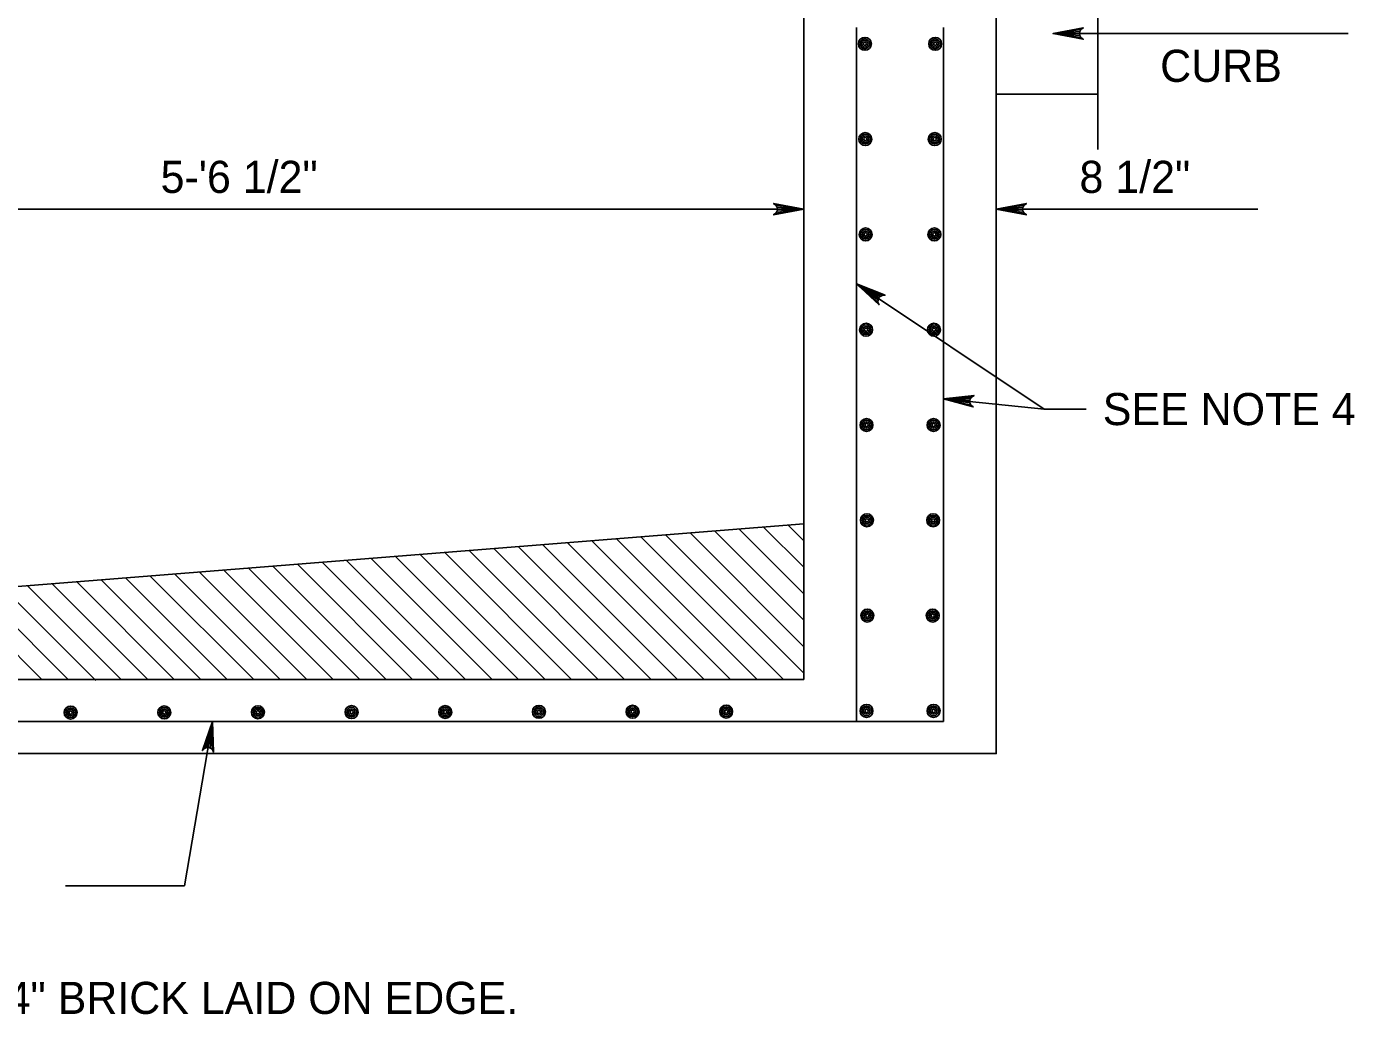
# Model space of a CAD drawing. Extents: x 2.4 to 9.7, y 1.1 to 11.2.
# Drawn here: x 7.045 to 9.526, y 8.136 to 9.981 of the extents above; entities that cross this region are included whole.
import ezdxf

# ---------------------------------------------------------------- set-up
doc = ezdxf.new("R2010")
doc.units = 0
for name, color, linetype in [('DETL-DIMS', 7, 'Continuous'), ('DETL-LINE', 7, 'Continuous'), ('DETL-NOTE', 7, 'Continuous'), ('DETL-PATT', 7, 'Continuous')]:
    doc.layers.add(name, color=color, linetype=linetype)

msp = doc.modelspace()

# ---------------------------------------------------------------- linework, layer by layer
at = {"layer": 'DETL-DIMS'}
for p, q in [((8.9629, 9.9678), (9.5146, 9.9678)), ((6.4511, 9.6398), (8.4972, 9.6398)), ((8.8568, 9.6398), (9.3453, 9.6398)), ((8.5958, 9.5003), (8.9462, 9.2664)), ((8.7582, 9.2855), (8.9462, 9.2664)), ((8.9462, 9.2664), (9.0251, 9.2664)), ((7.3923, 8.6829), (7.3404, 8.376)), ((7.3404, 8.376), (7.1175, 8.376))]:
    msp.add_line(p, q, dxfattribs=at)
for points in [[(8.9629, 9.9678), (9.0194, 9.9784), (9.0151, 9.9754), (9.0128, 9.9716), (9.0122, 9.9678), (9.0128, 9.964), (9.0151, 9.9602), (9.0194, 9.9572), (8.9629, 9.9678), (9.0151, 9.9602), (9.0128, 9.964), (8.9629, 9.9678), (9.0122, 9.9678), (9.0128, 9.9716), (8.9629, 9.9678), (9.0151, 9.9754)], [(8.4972, 9.6398), (8.4407, 9.6292), (8.4451, 9.6322), (8.4473, 9.636), (8.448, 9.6398), (8.4473, 9.6436), (8.4451, 9.6474), (8.4407, 9.6504), (8.4972, 9.6398), (8.4451, 9.6474), (8.4473, 9.6436), (8.4972, 9.6398), (8.448, 9.6398), (8.4473, 9.636), (8.4972, 9.6398), (8.4451, 9.6322)], [(8.8568, 9.6398), (8.9133, 9.6504), (8.9089, 9.6474), (8.9067, 9.6436), (8.906, 9.6398), (8.9067, 9.636), (8.9089, 9.6322), (8.9133, 9.6292), (8.8568, 9.6398), (8.9089, 9.6322), (8.9067, 9.636), (8.8568, 9.6398), (8.906, 9.6398), (8.9067, 9.6436), (8.8568, 9.6398), (8.9089, 9.6474)], [(8.5958, 9.5003), (8.6491, 9.4789), (8.6439, 9.4787), (8.6399, 9.4767), (8.6373, 9.4739), (8.6359, 9.4703), (8.6357, 9.4659), (8.6378, 9.4611), (8.5958, 9.5003), (8.6357, 9.4659), (8.6359, 9.4703), (8.5958, 9.5003), (8.6373, 9.4739), (8.6399, 9.4767), (8.5958, 9.5003), (8.6439, 9.4787)], [(8.7582, 9.2855), (8.8153, 9.2916), (8.8108, 9.2889), (8.8082, 9.2853), (8.8073, 9.2816), (8.8076, 9.2778), (8.8096, 9.2738), (8.8137, 9.2705), (8.7582, 9.2855), (8.8096, 9.2738), (8.8076, 9.2778), (8.7582, 9.2855), (8.8073, 9.2816), (8.8082, 9.2853), (8.7582, 9.2855), (8.8108, 9.2889)], [(7.3923, 8.6829), (7.3945, 8.6255), (7.3922, 8.6302), (7.3888, 8.633), (7.3851, 8.6342), (7.3813, 8.6341), (7.3772, 8.6324), (7.3736, 8.6286), (7.3923, 8.6829), (7.3772, 8.6324), (7.3813, 8.6341), (7.3923, 8.6829), (7.3851, 8.6342), (7.3888, 8.633), (7.3923, 8.6829), (7.3922, 8.6302)]]:
    msp.add_lwpolyline(points, dxfattribs=at)
at = {"layer": 'DETL-LINE'}
for p, q in [((8.8568, 8.6227), (8.8568, 10.6227)), ((8.4972, 8.7614), (8.4972, 10.5136)), ((9.0468, 10.2538), (9.0468, 9.7514)), ((8.5958, 8.6829), (8.5958, 9.979)), ((8.7582, 8.6829), (8.7582, 9.979)), ((9.0468, 9.8543), (8.8568, 9.8543)), ((6.4511, 8.8886), (8.4972, 9.052)), ((6.4511, 8.7614), (8.4972, 8.7614)), ((6.3547, 8.6829), (8.5958, 8.6829)), ((8.5958, 8.6829), (8.7582, 8.6829)), ((6.0916, 8.6227), (8.8568, 8.6227))]:
    msp.add_line(p, q, dxfattribs=at)
for centre, radius in [((8.6113, 9.9486), 0.0121), ((8.6113, 9.9486), 0.00909), ((8.6113, 9.9486), 0.00606), ((8.6113, 9.9486), 0.00303), ((8.7427, 9.9486), 0.0121), ((8.7427, 9.9486), 0.00909), ((8.7427, 9.9486), 0.00606), ((8.7427, 9.9486), 0.00303), ((8.6121, 9.7706), 0.0121), ((8.6121, 9.7706), 0.00909), ((8.6121, 9.7706), 0.00606), ((8.7419, 9.7706), 0.0121), ((8.7419, 9.7706), 0.00909), ((8.7419, 9.7706), 0.00606), ((8.6121, 9.7706), 0.00303), ((8.7419, 9.7706), 0.00303), ((8.6128, 9.5926), 0.0121), ((8.7412, 9.5926), 0.0121), ((8.6128, 9.5926), 0.00909), ((8.6128, 9.5926), 0.00606), ((8.6128, 9.5926), 0.00303), ((8.7412, 9.5926), 0.00909), ((8.7412, 9.5926), 0.00606), ((8.7412, 9.5926), 0.00303), ((8.6136, 9.4146), 0.0121), ((8.6136, 9.4146), 0.00909), ((8.6136, 9.4146), 0.00606), ((8.6136, 9.4146), 0.00303), ((8.7404, 9.4146), 0.0121), ((8.7404, 9.4146), 0.00909), ((8.7404, 9.4146), 0.00606), ((8.7404, 9.4146), 0.00303), ((8.6144, 9.2366), 0.0121), ((8.6144, 9.2366), 0.00909), ((8.6144, 9.2366), 0.00606), ((8.6144, 9.2366), 0.00303), ((8.7396, 9.2366), 0.0121), ((8.7396, 9.2366), 0.00909), ((8.7396, 9.2366), 0.00606), ((8.7396, 9.2366), 0.00303), ((8.6151, 9.0586), 0.0121), ((8.6151, 9.0586), 0.00909), ((8.6151, 9.0586), 0.00606), ((8.6151, 9.0586), 0.00303), ((8.7389, 9.0586), 0.0121), ((8.7389, 9.0586), 0.00909), ((8.7389, 9.0586), 0.00606), ((8.7389, 9.0586), 0.00303), ((8.6159, 8.8806), 0.0121), ((8.6159, 8.8806), 0.00909), ((8.6159, 8.8806), 0.00606), ((8.6159, 8.8806), 0.00303), ((8.7381, 8.8806), 0.0121), ((8.7381, 8.8806), 0.00909), ((8.7381, 8.8806), 0.00606), ((8.7381, 8.8806), 0.00303), ((7.1273, 8.6995), 0.0121), ((7.1273, 8.6995), 0.00909), ((7.3023, 8.6998), 0.0121), ((7.3023, 8.6998), 0.00909), ((7.4772, 8.7), 0.0121), ((7.4772, 8.7), 0.00909), ((7.6522, 8.7003), 0.0121), ((7.6522, 8.7003), 0.00909), ((7.8272, 8.7005), 0.0121), ((7.8272, 8.7005), 0.00909), ((8.0022, 8.7008), 0.0121), ((8.0022, 8.7008), 0.00909), ((8.1772, 8.701), 0.0121), ((8.1772, 8.701), 0.00909), ((8.3522, 8.7013), 0.0121), ((8.3522, 8.7013), 0.00909), ((8.6144, 8.7026), 0.0121), ((8.6144, 8.7026), 0.00909), ((8.6144, 8.7026), 0.00606), ((8.7396, 8.7026), 0.0121), ((8.7396, 8.7026), 0.00909), ((8.7396, 8.7026), 0.00606), ((7.1273, 8.6995), 0.00606), ((7.1273, 8.6995), 0.00303), ((7.3023, 8.6998), 0.00606), ((7.3023, 8.6998), 0.00303), ((7.4772, 8.7), 0.00606), ((7.4772, 8.7), 0.00303), ((7.6522, 8.7003), 0.00606), ((7.6522, 8.7003), 0.00303), ((7.8272, 8.7005), 0.00606), ((7.8272, 8.7005), 0.00303), ((8.0022, 8.7008), 0.00606), ((8.0022, 8.7008), 0.00303), ((8.1772, 8.701), 0.00606), ((8.1772, 8.701), 0.00303), ((8.3522, 8.7013), 0.00606), ((8.3522, 8.7013), 0.00303), ((8.6144, 8.7026), 0.00303), ((8.7396, 8.7026), 0.00303)]:
    msp.add_circle(centre, radius, dxfattribs=at)
at = {"layer": 'DETL-PATT'}
for p, q in [((8.2388, 9.0313), (8.4972, 8.773)), ((8.2847, 9.035), (8.4972, 8.8225)), ((8.3305, 9.0387), (8.4972, 8.872)), ((8.3764, 9.0423), (8.4972, 8.9215)), ((8.4222, 9.046), (8.4972, 8.971)), ((8.468, 9.0496), (8.4972, 9.0205)), ((7.9638, 9.0094), (8.2118, 8.7614)), ((8.0097, 9.013), (8.2613, 8.7614)), ((8.0555, 9.0167), (8.3108, 8.7614)), ((8.1013, 9.0204), (8.3603, 8.7614)), ((8.1472, 9.024), (8.4098, 8.7614)), ((8.193, 9.0277), (8.4593, 8.7614)), ((7.6429, 8.9838), (7.8654, 8.7614)), ((7.6888, 8.9874), (7.9148, 8.7614)), ((7.7346, 8.9911), (7.9643, 8.7614)), ((7.7805, 8.9947), (8.0138, 8.7614)), ((7.8263, 8.9984), (8.0633, 8.7614)), ((7.8721, 9.0021), (8.1128, 8.7614)), ((7.918, 9.0057), (8.1623, 8.7614)), ((7.3221, 8.9582), (7.5189, 8.7614)), ((7.3679, 8.9618), (7.5684, 8.7614)), ((7.4138, 8.9655), (7.6179, 8.7614)), ((7.4596, 8.9691), (7.6674, 8.7614)), ((7.5054, 8.9728), (7.7169, 8.7614)), ((7.5513, 8.9765), (7.7664, 8.7614)), ((7.5971, 8.9801), (7.8159, 8.7614)), ((7.0012, 8.9325), (7.1744, 8.7593)), ((7.047, 8.9362), (7.2219, 8.7614)), ((7.0929, 8.9399), (7.2714, 8.7614)), ((7.1387, 8.9435), (7.3209, 8.7614)), ((7.1846, 8.9472), (7.3704, 8.7614)), ((7.2304, 8.9508), (7.4199, 8.7614)), ((7.2762, 8.9545), (7.4694, 8.7614)), ((6.9095, 8.9252), (7.0734, 8.7614)), ((6.9554, 8.9289), (7.1229, 8.7614))]:
    msp.add_line(p, q, dxfattribs=at)
msp.add_lwpolyline([(6.0916, 8.8462), (6.4511, 8.8462), (6.4511, 8.7614), (8.4972, 8.7614), (8.4972, 10.196), (8.8568, 10.1936), (8.8568, 8.6227), (6.0916, 8.6227)], close=True, dxfattribs=at)

# ---------------------------------------------------------------- texts
at = {"layer": 'DETL-NOTE'}
for s, p in [('CURB', (9.1631, 9.8775)), ('5-\'6 1/2"', (7.2954, 9.6701)), ('8 1/2"', (9.0123, 9.6701)), ('SEE NOTE 4', (9.0558, 9.2364)), ('INVERT MAY BE PLAIN CONCRETE OR 4" BRICK LAID ON EDGE.', (5.4964, 8.1365))]:
    msp.add_text(s, height=0.06, dxfattribs=at).set_placement(p)

doc.saveas('drawing.dxf')
